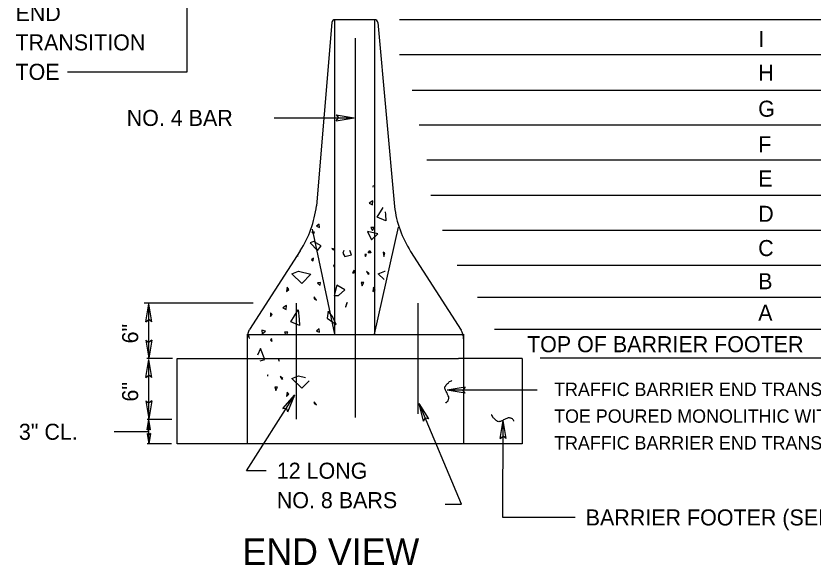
# Model space of a CAD drawing. Extents: x -0.8 to 6.5, y 10.6 to 20.8.
# Drawn here: x -0.775 to 2.206, y 17.122 to 19.175 of the extents above; entities that cross this region are included whole.
import ezdxf

# ---------------------------------------------------------------- set-up
doc = ezdxf.new("R2010")
doc.units = 0
for name, color, linetype in [('DETL-DIMS', 7, 'Continuous'), ('DETL-LINE', 7, 'Continuous'), ('DETL-NOTE', 7, 'Continuous'), ('DETL-PATT', 7, 'Continuous'), ('DETL-TITL', 7, 'Continuous')]:
    doc.layers.add(name, color=color, linetype=linetype)

msp = doc.modelspace()

# ---------------------------------------------------------------- linework, layer by layer
at = {"layer": 'DETL-DIMS'}
for p, q in [((-0.1345, 18.9657), (-0.1345, 19.2814)), ((5.9505, 19.1603), (0.6594, 19.1603)), ((5.5858, 19.0295), (0.6594, 19.0295)), ((-0.5824, 18.9657), (-0.1345, 18.9657)), ((5.2342, 18.8965), (0.7074, 18.8965)), ((0.1908, 18.7935), (0.4896, 18.7935)), ((0.4223, 18.8047), (0.4896, 18.7935)), ((0.4223, 18.8047), (0.4308, 18.7935)), ((0.4223, 18.7824), (0.4896, 18.7935)), ((0.4223, 18.7824), (0.4308, 18.7935)), ((4.8827, 18.7657), (0.7326, 18.7657)), ((0.8519, 18.6349), (0.762, 18.6349)), ((4.5313, 18.6349), (0.8519, 18.6349)), ((4.1798, 18.5039), (0.7767, 18.5039)), ((3.8286, 18.3731), (0.8207, 18.3731)), ((3.4771, 18.2423), (0.8754, 18.2423)), ((0.112, 18.1013), (-0.2955, 18.1013)), ((3.0449, 18.1223), (0.9508, 18.1223)), ((-0.2895, 18.0313), (-0.2783, 18.0985)), ((-0.2783, 17.8952), (-0.2783, 18.0985)), ((-0.267, 18.0313), (-0.2783, 18.0985)), ((-0.2895, 18.0313), (-0.2783, 18.0396)), ((-0.267, 18.0313), (-0.2783, 18.0396)), ((2.8326, 18.0023), (1.0143, 18.0023)), ((-0.2895, 17.9623), (-0.2783, 17.8952)), ((-0.2895, 17.9623), (-0.2783, 17.954)), ((-0.267, 17.9623), (-0.2783, 17.8952)), ((-0.267, 17.9623), (-0.2783, 17.954)), ((-0.1893, 17.8937), (-0.286, 17.8937)), ((2.8042, 17.8953), (1.186, 17.8953)), ((-0.2895, 17.8232), (-0.2783, 17.8903)), ((-0.2783, 17.6684), (-0.2783, 17.8903)), ((-0.267, 17.8232), (-0.2783, 17.8903)), ((-0.2895, 17.8232), (-0.2783, 17.8317)), ((-0.267, 17.8232), (-0.2783, 17.8317)), ((0.9045, 17.7874), (0.8374, 17.7762)), ((1.1743, 17.7762), (0.8374, 17.7762)), ((0.9045, 17.7649), (0.8374, 17.7762)), ((0.9045, 17.7874), (0.896, 17.7762)), ((0.9045, 17.7649), (0.896, 17.7762)), ((0.0872, 17.4746), (0.2683, 17.7577)), ((0.2226, 17.707), (0.2683, 17.7577)), ((0.2415, 17.695), (0.2683, 17.7577)), ((-0.2895, 17.7355), (-0.2783, 17.6684)), ((-0.2895, 17.7355), (-0.2783, 17.7272)), ((-0.267, 17.7355), (-0.2783, 17.6684)), ((-0.267, 17.7355), (-0.2783, 17.7272)), ((0.8915, 17.3491), (0.7332, 17.7255)), ((0.7489, 17.6592), (0.7332, 17.7255)), ((0.7695, 17.6679), (0.7332, 17.7255)), ((0.2226, 17.707), (0.2366, 17.7082)), ((0.2415, 17.695), (0.2366, 17.7082)), ((-0.2846, 17.6269), (-0.2783, 17.6654)), ((-0.2845, 17.6674), (-0.1925, 17.6674)), ((-0.2783, 17.5751), (-0.2783, 17.6654)), ((-0.2718, 17.6269), (-0.2783, 17.6654)), ((0.7489, 17.6592), (0.756, 17.6712)), ((0.7695, 17.6679), (0.756, 17.6712)), ((1.0355, 17.5949), (1.0468, 17.662)), ((1.0463, 17.2999), (1.0468, 17.662)), ((1.058, 17.5949), (1.0468, 17.662)), ((-0.2846, 17.6269), (-0.2783, 17.6317)), ((-0.2718, 17.6269), (-0.2783, 17.6317)), ((-0.2783, 17.6202), (-0.4078, 17.6202)), ((-0.2846, 17.6135), (-0.2783, 17.5751)), ((-0.2846, 17.6135), (-0.2783, 17.6087)), ((-0.2718, 17.6135), (-0.2783, 17.5751)), ((-0.2718, 17.6135), (-0.2783, 17.6087)), ((1.0355, 17.5949), (1.0468, 17.6032)), ((1.058, 17.5949), (1.0468, 17.6032)), ((-0.194, 17.5751), (-0.2845, 17.5751)), ((0.1605, 17.4746), (0.0872, 17.4746)), ((0.8304, 17.3491), (0.8915, 17.3491)), ((1.316, 17.2999), (1.0463, 17.2999))]:
    msp.add_line(p, q, dxfattribs=at)
for points in [[(0.8309, 17.7285), (0.8352, 17.73), (0.8382, 17.7329), (0.841, 17.7359), (0.8425, 17.7402), (0.8439, 17.7444), (0.8439, 17.7502), (0.8395, 17.7589), (0.8382, 17.7632), (0.8339, 17.7704), (0.8295, 17.7819), (0.8295, 17.7877), (0.8324, 17.792), (0.8367, 17.7978), (0.8425, 17.8035), (0.8467, 17.8078), (0.854, 17.8107), (0.8554, 17.8122)], [(1.0873, 17.6592), (1.0858, 17.6635), (1.083, 17.6665), (1.0802, 17.6694), (1.0758, 17.6709), (1.0715, 17.6722), (1.0657, 17.6722), (1.057, 17.6679), (1.0527, 17.6665), (1.0455, 17.6622), (1.034, 17.6579), (1.0282, 17.6579), (1.0238, 17.6607), (1.0182, 17.665), (1.0123, 17.6709), (1.008, 17.675), (1.0052, 17.6824), (1.0037, 17.6837)]]:
    msp.add_spline(points, degree=3, dxfattribs=at)
at = {"layer": 'DETL-LINE'}
for p, q in [((0.4059, 19.1495), (0.3488, 18.4649)), ((0.4179, 17.9853), (0.4179, 19.1603)), ((0.5662, 19.1603), (0.4179, 19.1603)), ((0.5662, 19.1603), (0.5662, 17.9853)), ((0.5782, 19.1496), (0.6407, 18.4622)), ((0.4931, 19.091), (0.4931, 17.674)), ((0.4179, 17.9853), (0.3334, 18.3771)), ((0.5662, 17.9853), (0.6554, 18.3851)), ((0.0998, 18.0028), (0.2885, 18.2969)), ((0.7011, 18.2943), (0.8895, 18.0001)), ((0.273, 18.1013), (0.273, 17.6674)), ((0.7284, 18.1013), (0.7284, 17.6875)), ((0.8965, 17.983), (0.0878, 17.983)), ((0.0905, 17.5746), (0.0905, 17.9853)), ((0.899, 17.9853), (0.899, 17.5746)), ((-0.172, 17.5746), (-0.172, 17.894)), ((-0.172, 17.894), (0.0715, 17.894)), ((0.0715, 17.894), (0.88, 17.894)), ((1.118, 17.894), (0.88, 17.894)), ((1.118, 17.894), (1.118, 17.5746)), ((1.118, 17.5746), (-0.172, 17.5746))]:
    msp.add_line(p, q, dxfattribs=at)
for centre, radius, start, end in [((0.418, 19.1483), 0.012, 90, 174.0907), ((0.5662, 19.1483), 0.012, 6.4211, 90), ((-0.0484, 18.5127), 0.4, 327.3444, 353.1231), ((1.0378, 18.5101), 0.4, 186.8769, 212.6556), ((0.1504, 17.9729), 0.06, 151.6959, 180), ((0.839, 17.9678), 0.06, 0, 32.6557)]:
    msp.add_arc(centre, radius, start, end, dxfattribs=at)
at = {"layer": 'DETL-PATT'}
for points in [[(0.5607, 18.5402), (0.5601, 18.5357), (0.5619, 18.5376)], [(0.6056, 18.4421), (0.6066, 18.4326), (0.6086, 18.4086), (0.5764, 18.4224), (0.5979, 18.4589)], [(0.2775, 18.2781), (0.2778, 18.2751), (0.2795, 18.2814)], [(0.4516, 18.2973), (0.4473, 18.2876), (0.4554, 18.2751), (0.4794, 18.2813), (0.4733, 18.2973)], [(0.6021, 18.189), (0.5802, 18.2108), (0.6047, 18.2209), (0.6056, 18.2206)], [(0.0977, 17.9703), (0.0978, 17.9703), (0.0958, 17.9803), (0.0937, 17.9788)], [(0.2376, 17.9853), (0.2413, 17.9923), (0.2293, 17.9923), (0.2328, 17.9853)], [(0.1388, 17.8852), (0.1563, 17.8897), (0.14, 17.932), (0.1288, 17.9062)], [(0.2106, 17.8917), (0.2068, 17.8917), (0.2086, 17.8835), (0.2106, 17.8872)], [(0.1665, 17.8282), (0.1665, 17.833), (0.1651, 17.8308)], [(0.3211, 17.8102), (0.2936, 17.7827), (0.2571, 17.8192), (0.2816, 17.8292), (0.3078, 17.8225)]]:
    msp.add_lwpolyline(points, dxfattribs=at)
for points in [[(0.5461, 18.4752), (0.5581, 18.4691), (0.5601, 18.4834)], [(0.3584, 18.3966), (0.3484, 18.3884), (0.3604, 18.3841)], [(0.5399, 18.3683), (0.5542, 18.3379), (0.5782, 18.3601)], [(0.5524, 18.3841), (0.5581, 18.3721), (0.5644, 18.3841)], [(0.3321, 18.3663), (0.3383, 18.3601), (0.3421, 18.3663)], [(0.3258, 18.3259), (0.3523, 18.2976), (0.3666, 18.3154), (0.3383, 18.3318)], [(0.4128, 18.3034), (0.4069, 18.3054), (0.4128, 18.2996)], [(0.5297, 18.2833), (0.5317, 18.2751), (0.5361, 18.2833)], [(0.5481, 18.2976), (0.5524, 18.2894), (0.5422, 18.2894)], [(0.5984, 18.2914), (0.6009, 18.2751), (0.6047, 18.2894)], [(0.3301, 18.2631), (0.3359, 18.2593), (0.3383, 18.2693)], [(0.2816, 18.2209), (0.3283, 18.209), (0.2936, 18.1743), (0.2571, 18.2108)], [(0.4169, 18.2449), (0.4128, 18.2411), (0.4151, 18.2368)], [(0.4894, 18.2248), (0.4838, 18.2146), (0.4894, 18.2146)], [(0.5422, 18.209), (0.5461, 18.2108), (0.5361, 18.2189)], [(0.2395, 18.1605), (0.237, 18.1441), (0.2451, 18.1523)], [(0.3523, 18.1763), (0.3623, 18.1681), (0.3643, 18.1781)], [(0.4309, 18.1296), (0.4554, 18.1503), (0.4251, 18.1681), (0.4151, 18.1296)], [(0.5159, 18.1781), (0.5198, 18.1661), (0.5259, 18.1781)], [(0.5624, 18.1605), (0.5601, 18.1441), (0.5682, 18.1523)], [(0.3403, 18.124), (0.3403, 18.1176), (0.3484, 18.112)], [(0.4573, 18.0875), (0.4593, 18.0875), (0.4631, 18.1038)], [(0.2231, 18.0836), (0.2351, 18.0773), (0.237, 18.0918)], [(0.2836, 18.0408), (0.2855, 18.0168), (0.2533, 18.0308), (0.2798, 18.0755)], [(0.3926, 18.0711), (0.3888, 18.0451), (0.4228, 18.0206), (0.4089, 18.051)], [(0.1765, 18.0653), (0.1765, 18.051), (0.1828, 18.0591)], [(0.1443, 18.0005), (0.1463, 17.9867), (0.1583, 17.9967)], [(0.3584, 18.0048), (0.3484, 17.9967), (0.3604, 17.9923)], [(0.1765, 17.9622), (0.1828, 17.9583), (0.1808, 17.9683)], [(0.2193, 17.8172), (0.2231, 17.8192), (0.213, 17.8273)], [(0.1928, 17.7865), (0.1966, 17.7745), (0.203, 17.7865)], [(0.2395, 17.7687), (0.237, 17.7524), (0.2451, 17.7605)], [(0.3403, 17.7322), (0.3403, 17.726), (0.3484, 17.7202)]]:
    msp.add_lwpolyline(points, close=True, dxfattribs=at)

# ---------------------------------------------------------------- texts
at = {"layer": 'DETL-NOTE'}
for s, height, p in [('END', 0.06, (-0.7771, 19.1556)), ('I', 0.06, (2.0012, 19.0589)), ('TRANSITION', 0.06, (-0.7771, 19.0457)), ('TOE', 0.06, (-0.7771, 18.9357)), ('H', 0.06, (2.0012, 18.9327)), ('G', 0.06, (2.0012, 18.7978)), ('NO. 4 BAR', 0.06, (-0.361, 18.7634)), ('F', 0.06, (2.0012, 18.6647)), ('E', 0.06, (2.0012, 18.5369)), ('D', 0.06, (2.0012, 18.405)), ('C', 0.06, (2.0012, 18.2769)), ('B', 0.06, (2.0012, 18.153)), ('A', 0.06, (2.0012, 18.035)), ('TOP OF BARRIER FOOTER', 0.06, (1.1366, 17.9176)), ('TRAFFIC BARRIER END TRANSITION', 0.05, (1.2378, 17.7538)), ('TOE POURED MONOLITHIC WITH THE', 0.05, (1.2378, 17.6538)), ('3" CL.', 0.06, (-0.7642, 17.5901)), ('TRAFFIC BARRIER END TRANSITION', 0.05, (1.2378, 17.5537)), ('12 LONG', 0.06, (0.2004, 17.4445)), ('NO. 8 BARS', 0.06, (0.2004, 17.3345)), ('BARRIER FOOTER (SEE NOTE 1)', 0.06, (1.356, 17.2699))]:
    msp.add_text(s, height=height, dxfattribs=at).set_placement(p)
for p in [(-0.3182, 17.9504), (-0.3182, 17.733)]:
    msp.add_text('6"', height=0.06, rotation=90, dxfattribs=at).set_placement(p)
at = {"layer": 'DETL-TITL'}
msp.add_text('END VIEW', height=0.1, dxfattribs=at).set_placement((0.0721, 17.1219))

doc.saveas('drawing.dxf')
